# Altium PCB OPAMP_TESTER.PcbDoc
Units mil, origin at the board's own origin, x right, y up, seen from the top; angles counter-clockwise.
Board outline 7760.03 x 6155.03 mil, 2 copper layers (Top Layer, Bottom Layer); 148 components, 57 nets, 514 pads, 0 vias.
Unrouted connection lines stored in the file: 27.
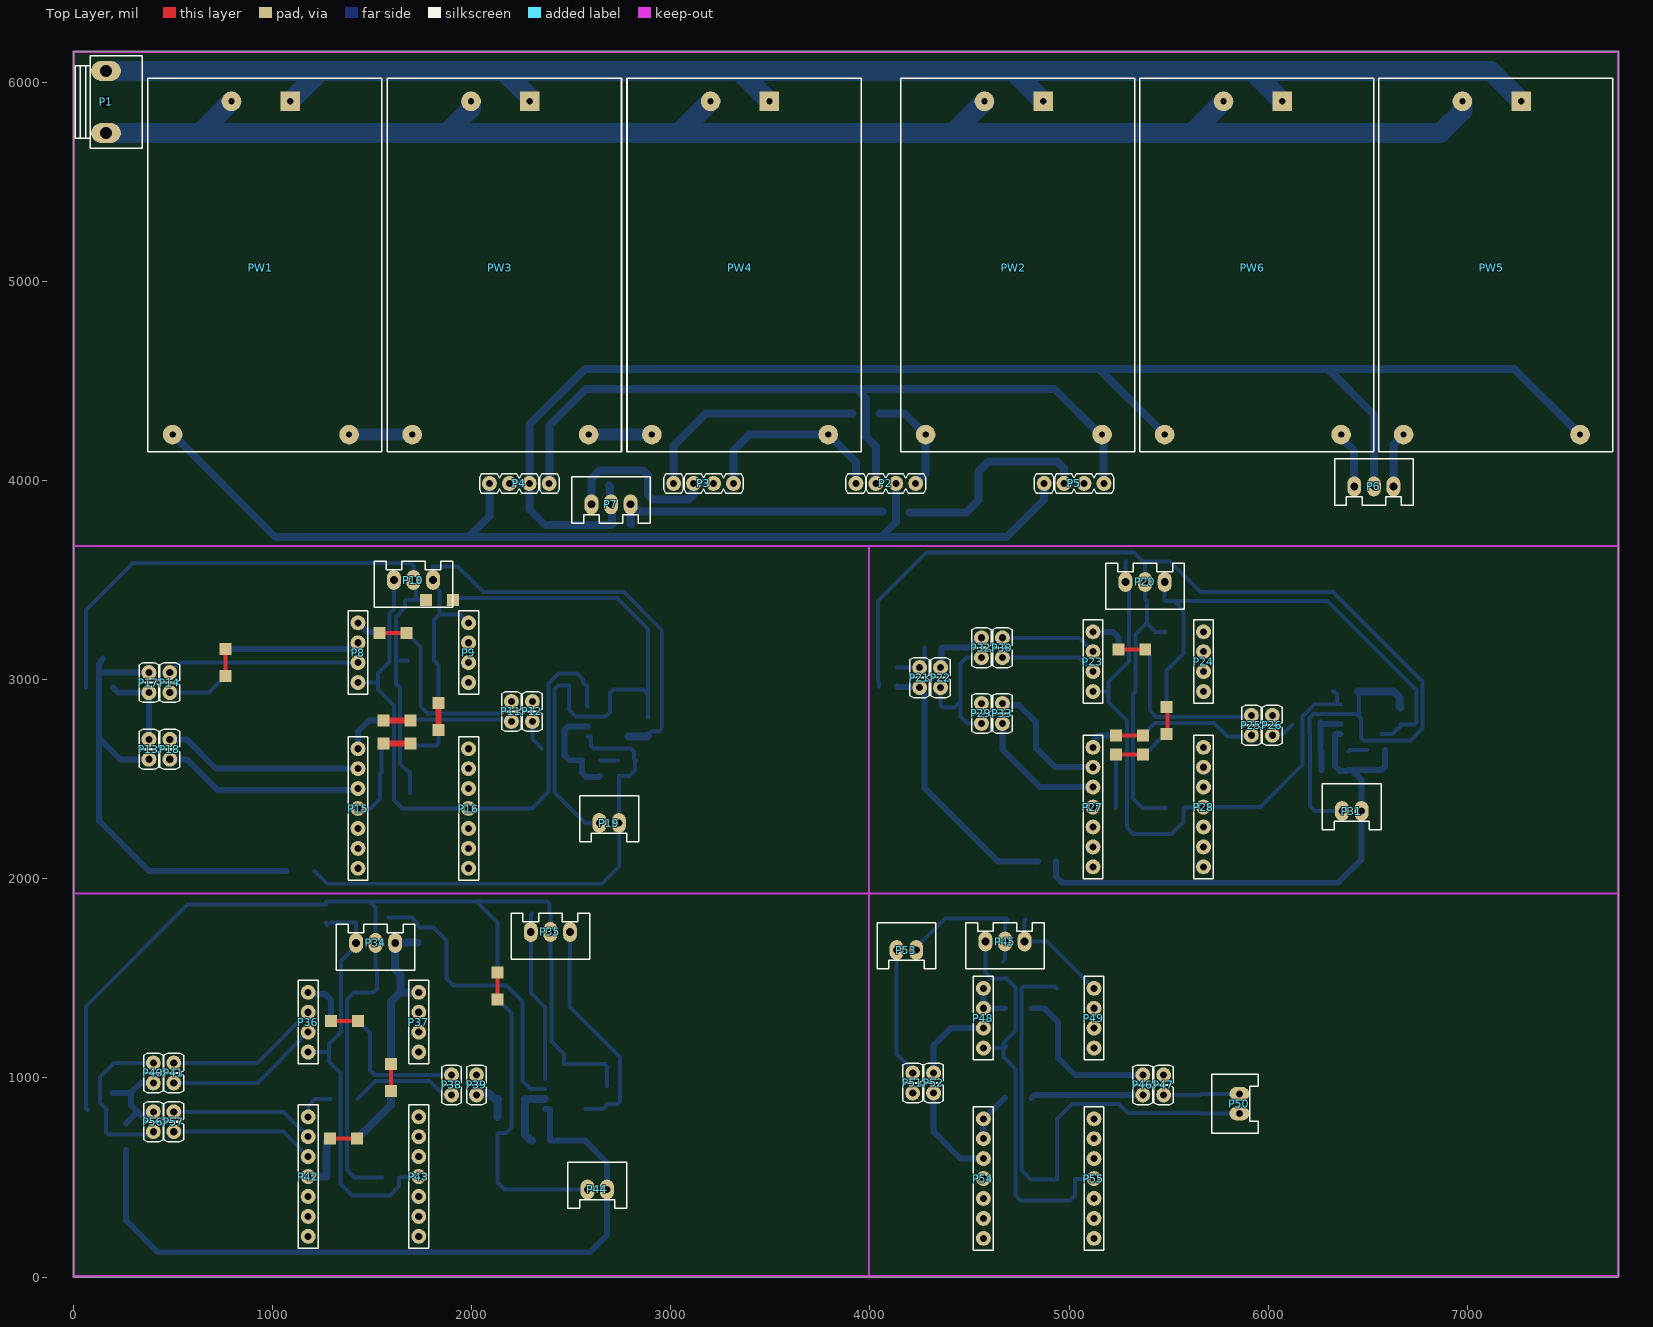
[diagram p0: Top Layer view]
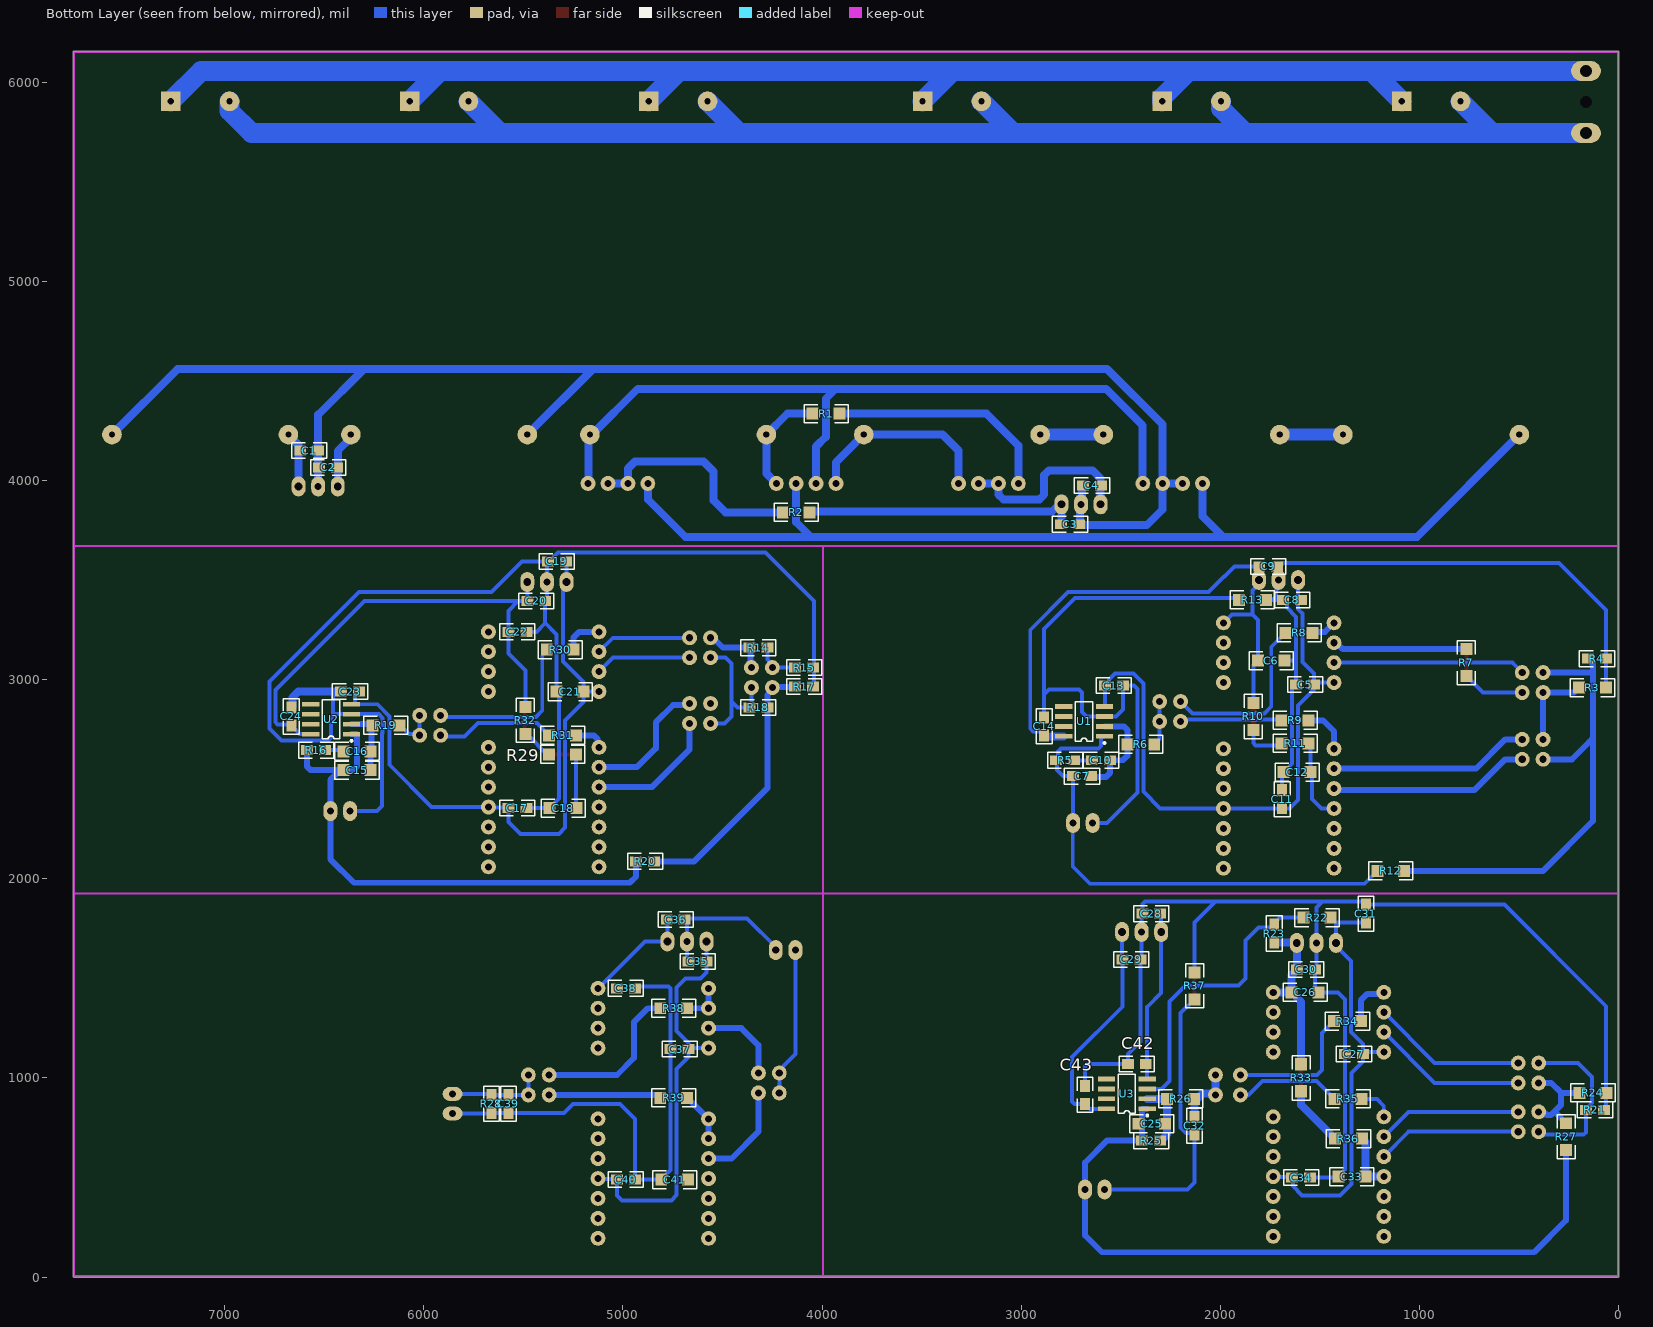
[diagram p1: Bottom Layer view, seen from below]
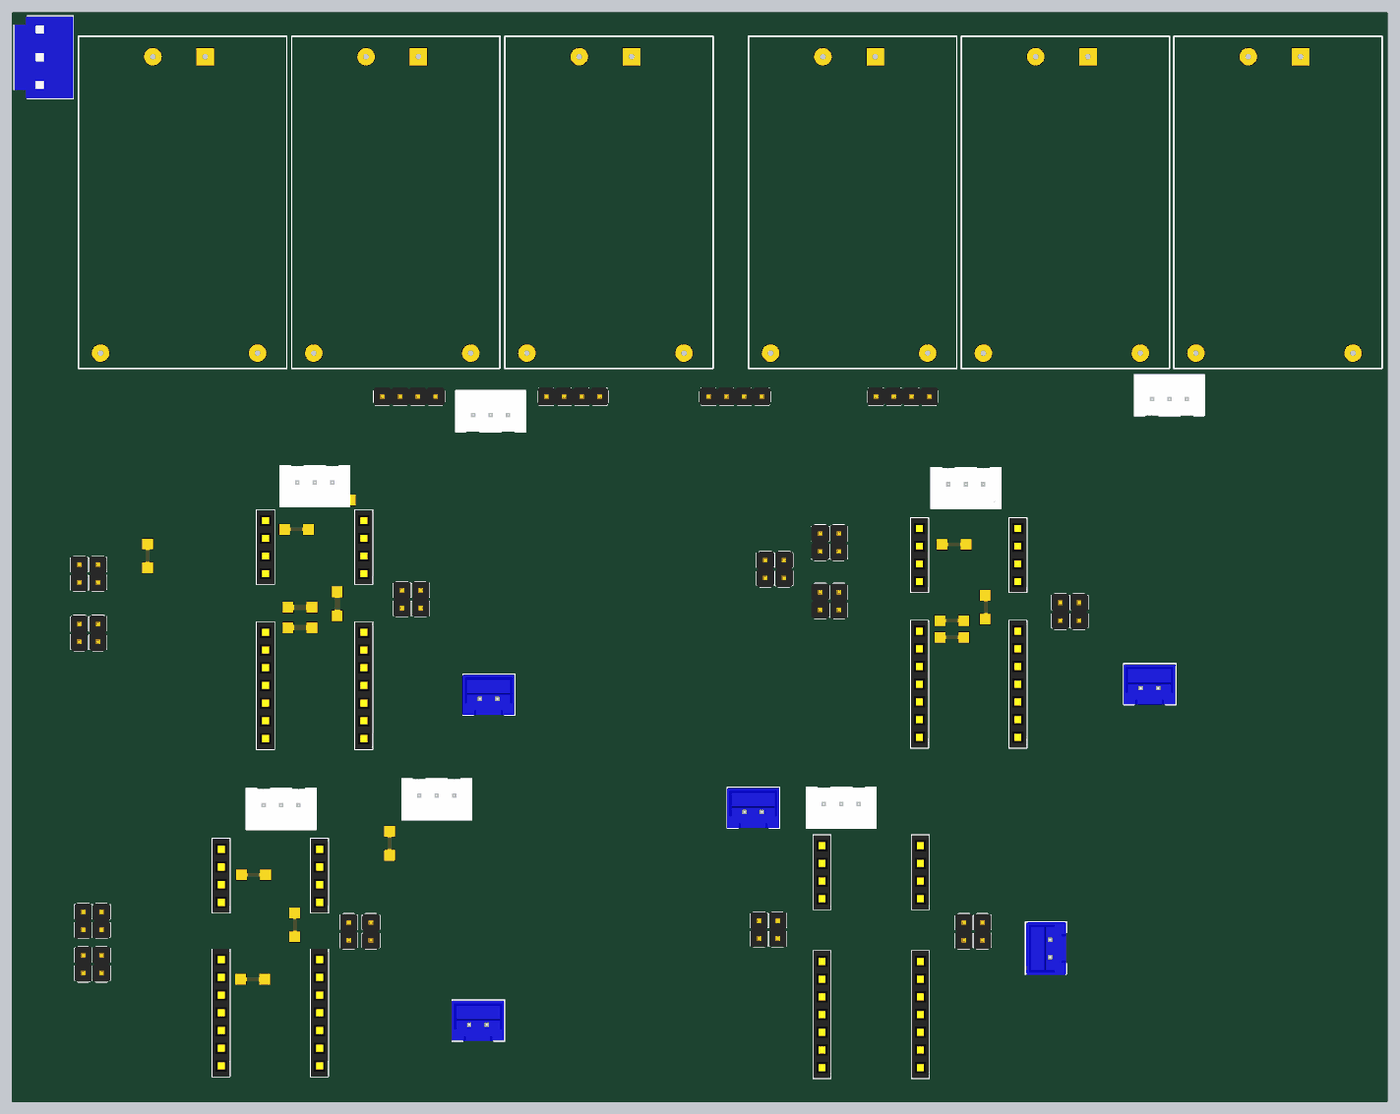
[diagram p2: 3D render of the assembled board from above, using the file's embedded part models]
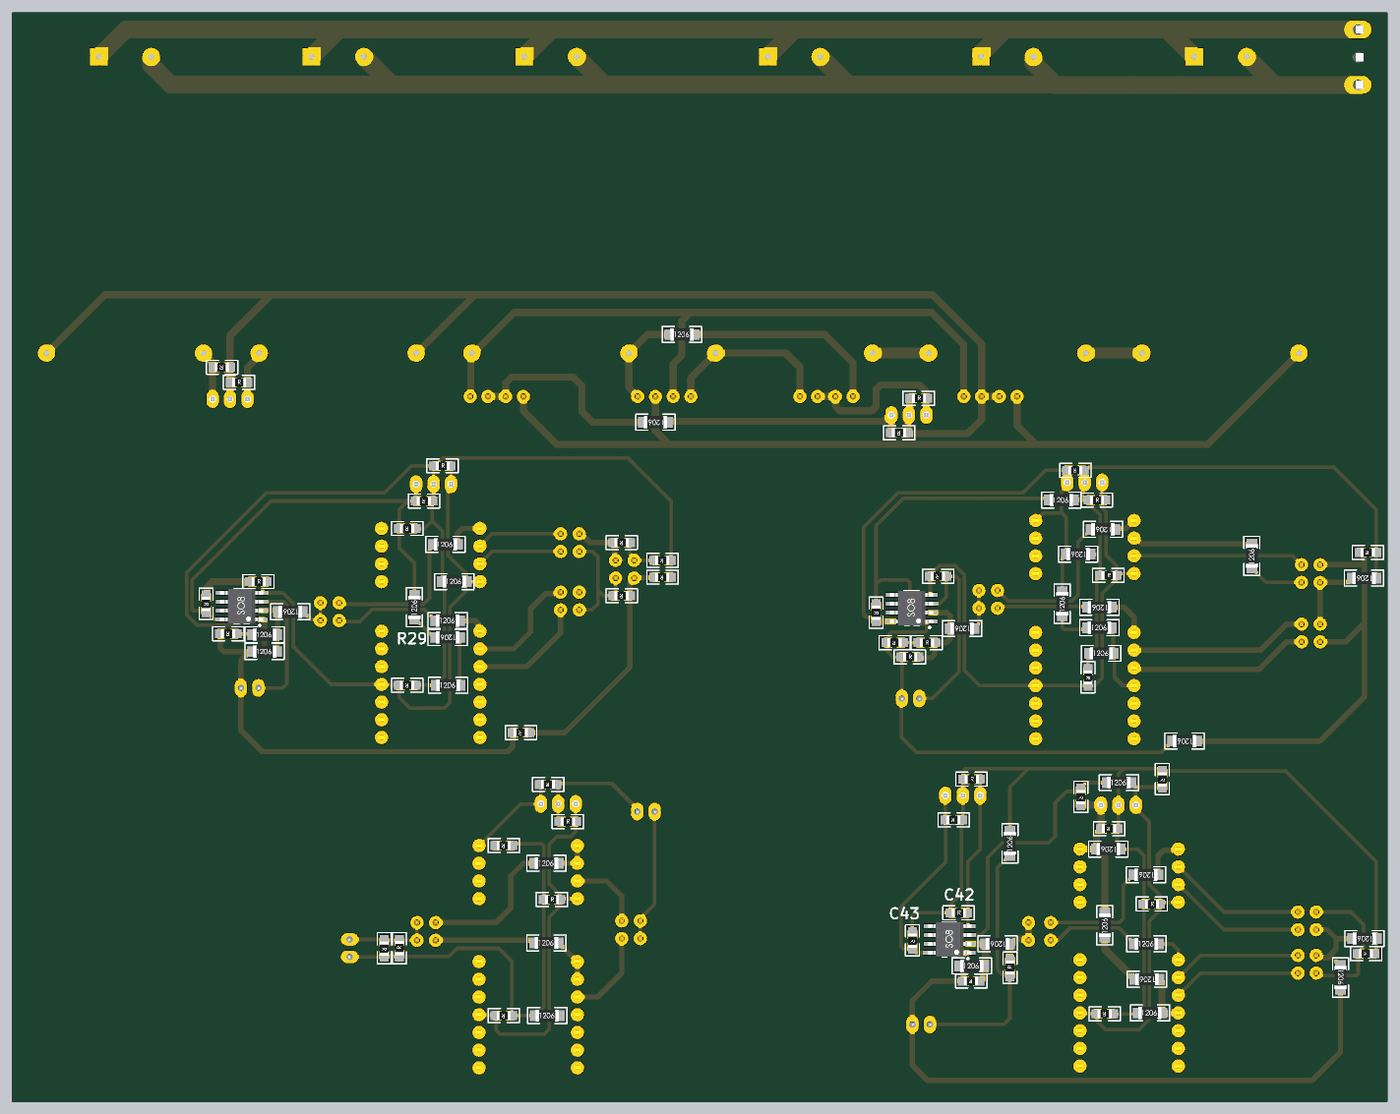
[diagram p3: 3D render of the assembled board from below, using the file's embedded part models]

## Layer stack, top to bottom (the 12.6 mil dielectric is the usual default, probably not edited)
Top Solder: solder mask 0.4, Solder Resist, Dk 3.5
Top Layer: signal copper 1.4
Dielectric 1: dielectric 12.6, FR-4, Dk 4.8
Bottom Layer: signal copper 1.4
Bottom Solder: solder mask 0.4, Solder Resist, Dk 3.5

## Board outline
5,-0.01 cw(c5,5) -0.01,5 -0.01,6150 cw(c5,6150) 5,6155.02 7755,6155.02 cw(c7755,6150) 7760.02,6150 7760.02,5 cw(c7755,5) 7755,-0.01

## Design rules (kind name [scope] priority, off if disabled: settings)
Clearance [All] p1: gap=10 ignorepadtopadclearanceinfootprint=FALSE except(0: Arc-Hole Track-Hole SMDPad-Hole THPad-Hole Via-Hole Fill-Hole Poly-Hole Region-Hole Text-Hole)
PolygonConnect [All] p1: connectstyle=Relief reliefconductorwidth=10 reliefentries=4 polygonreliefangle="90 Angle" airgapwidth=10
RoutingVias [All] p1: holewidth=28 width=50 viastyle="Through Hole" minholewidth=28 minwidth=50 maxholewidth=50 maxwidth=500
SolderMaskExpansion [All] p1: expansion=4 istentingtop=FALSE
Width [All] p1: maxlimit=100 minlimit=10 preferedwidth=10
30 further rules are at their usual default settings.

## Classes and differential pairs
component class OPAMP_TESTER: C1 C2 C3 C4 P1 P2 P3 P4 P5 P6 P7 PW1 PW2 PW3 PW4 PW5 PW6 R1 R2
component class OPAMP_TESTER_2: C25 C26 C27 C28 C29 C30 C31 C32 C33 C34 C35 C36 C37 C38 C39 C40 C41 C42 C43 P34 P35 P36 P37 P38 P39 P40 P41 P42 P43 P44 P45 P46 P47 P48 P49 P50 P51 P52 P53 P54 P55 P56 P57 R21 R22 R23 R24 R25 R26 R27 R28 R33 R34 R35 R36 R37 R38 R39 U3
component class OPAMP_TESTER_1: C5 C6 C7 C8 C9 C10 C11 C12 C13 C14 C15 C16 C17 C18 C19 C20 C21 C22 C23 C24 P8 P9 P10 P11 P12 P13 P14 P15 P16 P17 P18 P19 P20 P21 P22 P23 P24 P25 P26 P27 P28 P29 P30 P31 P32 P33 R3 R4 R5 R6 R7 R8 R9 R10 R11 R12 R13 R14 R15 R16 R17 R18 R19 R20 R29 R30 R31 R32 U1 U2

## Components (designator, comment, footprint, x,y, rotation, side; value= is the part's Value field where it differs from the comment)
C1 "100nF" "SMD 0805" 6575,4150 r0 bottom
C2 "100nF" "SMD 0805" 6480,4065 r180 bottom
C3 "100nF" "SMD 0805" 2755,3780 r0 bottom
C4 "100nF" "SMD 0805" 2645,3975 r180 bottom
C5 "100nF" "SMD 0805" 1575,2975 r180 bottom
C6 "100nF" "SMD 1206" 1745,3095 r0 bottom
C7 "1uF" "SMD 0805" 2695,2515 r180 bottom
C8 "100nF" "SMD 0805" 1640,3400 r180 bottom
C9 "100nF" "SMD 0805" 1760.21,3568.31 r0 bottom
C10 "1uF" "SMD 0805" 2600,2595 r180 bottom
C11 "100nF" "SMD 0805" 1690,2400 r270 bottom
C12 "100nF" "SMD 1206" 1615,2535 r180 bottom
C13 "100nF" "SMD 0805" 2535,2970 r0 bottom
C14 "100nF" "SMD 0805" 2885,2765 r270 bottom
C15 "1uF" "SMD 1206" 6335,2545 r180 bottom
C16 "1uF" "SMD 1206" 6335,2640 r180 bottom
C17 "100nF" "SMD 0805" 5530,2355 r0 bottom
C18 "100nF" "SMD 1206" 5300,2355 r180 bottom
C19 "100nF" "SMD 0805" 5331.66,3593.67 r180 bottom
C20 "100nF" "SMD 0805" 5435,3395 r0 bottom
C21 "100nF" "SMD 1206" 5265,2940 r180 bottom
C22 "100nF" "SMD 0805" 5530,3240 r0 bottom
C23 "100nF" "SMD 0805" 6370,2940 r180 bottom
C24 "100nF" "SMD 0805" 6665,2815 r270 bottom
C25 "1uF" "SMD 1206" 2345,770 r180 bottom
C26 "100nF" "SMD 1206" 1575,1430 r0 bottom
C27 "100nF" "SMD 0805" 1330,1120 r180 bottom
C28 "100nF" "SMD 0805" 2347.5,1824.77 r180 bottom
C29 "100nF" "SMD 0805" 2447.5,1594.77 r0 bottom
C30 "100nF" "SMD 0805" 1570,1545 r0 bottom
C31 "100nF" "SMD 0805" 1270,1825 r270 bottom
C32 "1uF" "SMD 0805" 2130,760 r90 bottom
C33 "100nF" "SMD 1206" 1340,505 r180 bottom
C34 "100nF" "SMD 0805" 1595,500 r0 bottom
C35 "100nF" "SMD 0805" 4625,1585 r180 bottom
C36 "100nF" "SMD 0805" 4735,1795 r0 bottom
C37 "100nF" "SMD 0805" 4715,1145 r180 bottom
C38 "100nF" "SMD 0805" 4985,1450 r0 bottom
C39 "100pF" "SMD 0805" 5575,870 r90 bottom
C40 "100nF" "SMD 0805" 4985,490 r0 bottom
C41 "100nF" "SMD 1206" 4740,490 r180 bottom
C42 "100nF" "SMD 0805" 2420,1070 r180 bottom
C43 "100nF" "SMD 0805" 2680,915 r270 bottom
P1 "CONNECTOR 3" "CON VH 3" 165,5744.09 r90 top
P2 "CONNECTOR 4" "CON HDR 2.54M 4" 3930,3985 r0 top
P3 "CONNECTOR 4" "CON HDR 2.54M 4" 3015,3985 r0 top
P4 "CONNECTOR 4" "CON HDR 2.54M 4" 2390,3985 r180 top
P5 "CONNECTOR 4" "CON HDR 2.54M 4" 4875,3985 r0 top
P6 "INPUT_12+-V" "CON XH 3" 6628.43,3970 r180 top
P7 "INPUT_12+-V" "CON XH 3" 2798.43,3880 r180 top
P8 "LM358_DUT" "CON HDR 2.54FM 4" 1430,3285 r270 top
P9 "LM358DUT" "CON HDR 2.54FM 4" 1985,3285 r270 top
P10 "INPUT_12+-V" "CON XH 3" 1610,3500 r0 top
P11 "CONNECTOR 2" "CON HDR 2.54M 2" 2200,2890 r270 top
P12 "CONNECTOR 2" "CON HDR 2.54M 2" 2305,2790 r90 top
P13 "CONNECTOR 2" "CON HDR 2.54M 2" 380,2700 r270 top
P14 "CONNECTOR 2" "CON HDR 2.54M 2" 485,3035 r270 top
P15 "LM324_DUT" "CON HDR 2.54FM 7" 1430,2652.78 r270 top
P16 "LM324_DUT" "CON HDR 2.54FM 7" 1985,2652.78 r270 top
P17 "CONNECTOR 2" "CON HDR 2.54M 2" 380,2935 r90 top
P18 "CONNECTOR 2" "CON HDR 2.54M 2" 485,2600 r90 top
P19 "SAMPLE_OUT" "CON XH 2" 2740,2280 r180 top
P20 "INPUT_12+-V" "CON XH 3" 5283.15,3490 r0 top
P21 "CONNECTOR 2" "CON HDR 2.54M 2" 4250,3060 r270 top
P22 "CONNECTOR 2" "CON HDR 2.54M 2" 4355,2960 r90 top
P23 "LM358_DUT" "CON HDR 2.54FM 4" 5120,3240 r270 top
P24 "LM358DUT" "CON HDR 2.54FM 4" 5675,3240 r270 top
P25 "CONNECTOR 2" "CON HDR 2.54M 2" 5915,2820.49 r270 top
P26 "CONNECTOR 2" "CON HDR 2.54M 2" 6020.16,2720.49 r90 top
P27 "LM324_DUT" "CON HDR 2.54FM 7" 5120,2660 r270 top
P28 "LM324_DUT" "CON HDR 2.54FM 7" 5675,2660 r270 top
P29 "CONNECTOR 2" "CON HDR 2.54M 2" 4560,2880 r270 top
P30 "CONNECTOR 2" "CON HDR 2.54M 2" 4665,3110 r90 top
P31 "SAMPLE_OUT" "CON XH 2" 6468.43,2340 r180 top
P32 "CONNECTOR 2" "CON HDR 2.54M 2" 4560,3210 r270 top
P33 "CONNECTOR 2" "CON HDR 2.54M 2" 4665,2780 r90 top
P34 "INPUT_25V,5V" "CON XH 3" 1420,1678.19 r0 top
P35 "INPUT_12+-V" "CON XH 3" 2297.46,1732.96 r0 top
P36 "LM358_DUT" "CON HDR 2.54FM 4" 1180,1430 r270 top
P37 "LM358DUT" "CON HDR 2.54FM 4" 1735,1430 r270 top
P38 "CONNECTOR 2" "CON HDR 2.54M 2" 1900,1015 r270 top
P39 "CONNECTOR 2" "CON HDR 2.54M 2" 2025,1015 r270 top
P40 "CONNECTOR 2" "CON HDR 2.54M 2" 402.33,1075 r270 top
P41 "CONNECTOR 2" "CON HDR 2.54M 2" 505,975 r90 top
P42 "LM324_DUT" "CON HDR 2.54FM 7" 1180,805 r270 top
P43 "LM324_DUT" "CON HDR 2.54FM 7" 1735,805 r270 top
P44 "SAMPLE_OUT" "CON XH 2" 2680,440 r180 top
P45 "INPUT_12+-V" "CON XH 3" 4580,1685 r0 top
P46 "CONNECTOR 2" "CON HDR 2.54M 2" 5370,1015 r270 top
P47 "CONNECTOR 2" "CON HDR 2.54M 2" 5475,915 r90 top
P48 "LM358_DUT" "CON HDR 2.54FM 4" 4570,1450 r270 top
P49 "LM358DUT" "CON HDR 2.54FM 4" 5125,1450 r270 top
P50 "SAMPLE_OUT" "CON XH 2" 5855,920 r270 top
P51 "CONNECTOR 2" "CON HDR 2.54M 2" 4215,925 r90 top
P52 "CONNECTOR 2" "CON HDR 2.54M 2" 4320,925 r90 top
P53 "INPUT_15V_100KHz" "CON XH 2" 4232.73,1641.69 r180 top
P54 "LM324_DUT" "CON HDR 2.54FM 7" 4570,795 r270 top
P55 "LM324_DUT" "CON HDR 2.54FM 7" 5125,795 r270 top
P56 "CONNECTOR 2" "CON HDR 2.54M 2" 402.33,730 r90 top
P57 "CONNECTOR 2" "CON HDR 2.54M 2" 505,730 r90 top
PW1 "15V_PW" POW 1090,6018.23 r270 top
PW2 "5V_PW" POW 4870.28,6018.23 r270 top
PW3 "15V_PW" POW 2292.78,6018.23 r270 top
PW4 "15V_PW" POW 3495.55,6018.23 r270 top
PW5 "15V_PW" POW 7270,6018.23 r270 top
PW6 "15V_PW" POW 6070.47,6018.23 r270 top
R1 "0R" "SMD 1206" 3980,4335 r180 bottom
R2 "0R" "SMD 1206" 4130,3840 r0 bottom
R3 "200R_1%" "SMD 1206" 132.5,2959.85 r0 bottom
R4 "200R_1%" "SMD 0805" 110,3105 r0 bottom
R5 "4.3K" "SMD 0805" 2780,2595 r0 bottom
R6 "4.3K" "SMD 1206" 2400,2675 r0 bottom
R7 "0R" "SMD 1206" 765,3085 r90 bottom
R8 "0R" "SMD 1206" 1605,3235 r0 bottom
R9 "0R" "SMD 1206" 1625,2795 r0 bottom
R10 "0R" "SMD 1206" 1835,2815 r90 bottom
R11 "0R" "SMD 1206" 1625,2680 r180 bottom
R12 "24K_1%" "SMD 1206" 1145,2040 r0 bottom
R13 "0R" "SMD 1206" 1840,3400 r180 bottom
R14 "1Meg" "SMD 0805" 4320,3160 r0 bottom
R15 "100R" "SMD 0805" 4090,3060 r0 bottom
R16 "10K" "SMD 0805" 6540,2645.63 r0 bottom
R17 "100R" "SMD 0805" 4090,2965 r0 bottom
R18 "1Meg" "SMD 0805" 4320,2860 r0 bottom
R19 "10K" "SMD 1206" 6190,2770 r0 bottom
R20 "10K" "SMD 0805" 4888.51,2087.64 r0 bottom
R21 "100R" "SMD 0805" 120,840 r0 bottom
R22 "20K" "SMD 1206" 1515,1805 r180 bottom
R23 "20K" "SMD 0805" 1730,1725 r270 bottom
R24 "100R" "SMD 1206" 130,925 r0 bottom
R25 "10K" "SMD 0805" 2348.19,685 r0 bottom
R26 "10K" "SMD 1206" 2200,895 r0 bottom
R27 "10K" "SMD 1206" 265,705 r270 bottom
R28 "2K" "SMD 0805" 5660,870 r270 bottom
R29 "0R" "SMD 1206" 5302.5,2625 r0 bottom
R30 "0R" "SMD 1206" 5315,3150 r180 bottom
R31 "0R" "SMD 1206" 5302.5,2720 r180 bottom
R32 "0R" "SMD 1206" 5490,2795 r90 bottom
R33 "0R" "SMD 1206" 1595,1000 r90 bottom
R34 "0R" "SMD 1206" 1362.5,1285 r0 bottom
R35 "0R" "SMD 1206" 1360,895 r180 bottom
R36 "0R" "SMD 1206" 1357.5,695 r0 bottom
R37 "0R" "SMD 1206" 2130,1462.5 r90 bottom
R38 "0R" "SMD 1206" 4745,1350 r180 bottom
R39 "0R" "SMD 1206" 4745,900 r180 bottom
U1 "IC LM358" "SMD IC SOP8" 2685,2790 r90 bottom
U2 "IC LM358" "SMD IC SOP8" 6465,2801.18 r90 bottom
U3 "IC LM358" "SMD IC SOP8" 2470,920 r90 bottom

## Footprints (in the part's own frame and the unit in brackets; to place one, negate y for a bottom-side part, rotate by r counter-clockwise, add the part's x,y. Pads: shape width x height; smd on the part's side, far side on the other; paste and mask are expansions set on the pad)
"CON HDR 2.54FM 4" [mm] "CONNECTOR PTCH:2.54MM"
  round 1.905 hole 0.9: 1(0,0) 2(2.54,0) 3(5.08,0) 4(7.62,0)
  silkscreen extent -1.52,-1.27 9.14,1.27, body extent -1.5,-1.24 9.16,1.26, height 5
"CON HDR 2.54FM 7" [mm] "CONNECTOR PTCH:2.54MM"
  round 1.905 hole 0.9: 1(0,0) 2(2.54,0) 3(5.08,0) 4(7.62,0) 5(10.16,0) 6(12.7,0) 7(15.24,0)
  silkscreen extent -1.52,-1.27 16.76,1.27, body extent -1.54,-1.24 16.74,1.26, height 5
"CON HDR 2.54M 2" [mm] "CONNECTOR PTCH:2.54MM"
  round 1.905 hole 0.9: 1(0,0) 2(2.54,0)
  silkscreen extent -1.27,-1.25 3.81,1.25, body extent -1.27,-1.27 3.81,1.27, height 8.89
"CON HDR 2.54M 4" [mm] "CONNECTOR PTCH:2.54MM"
  round 1.905 hole 0.9: 1(0,0) 2(2.54,0) 3(5.08,0) 4(7.62,0)
  silkscreen extent -1.27,-1.25 8.89,1.25, body extent -1.27,-1.27 8.89,1.27, height 8.89
"CON VH 3" [mm] "CONNECTOR PITCH:3.96MM"
  oval 2.54x3.81 hole 1.5: 1(0,0) 3(7.92,0)
  round 0 hole 1.5: 2(3.96,0)
  silkscreen extent -1.95,-4.6 9.87,3.9, body extent -1.95,-4.6 9.87,3.9, height 10.9
"CON XH 2" [mm] "CONNECTOR PITCH:2.5MM"
  oval 1.778x2.54 hole 0.9: 1(0,0) 2(2.5,0)
  silkscreen extent -2.5,-3.5 5,2.4, body extent -2.45,-3.35 5.05,2.35, height 7
"CON XH 3" [mm] "CONNECTOR PITCH:2.5MM"
  oval 1.778x2.54 hole 1: 1(0,0) 3(5,0)
  oval 1.778x2.54 hole 0.9: 2(2.5,0)
  silkscreen extent -2.5,-3.5 7.5,2.4, body extent -2.46,-3.41 7.44,2.34, height 7
POW [mm]
  rect 2.5x2.5 hole 0.8: 1(2.921,0)
  round 2.5 hole 0.8: 2(2.921,-7.5) 3(45.421,-15) 4(45.421,7.5)
  silkscreen extent 0,-18.16 47.63,11.68
"SMD 0805" [mil] "SMD 0805"
  round 27.56 on Mech2: 0(0,0)
  rect 60x50 smd: 1(-45,0) 2(45,0)
  silkscreen extent -88,-39 88,39, body extent -57,-28 61,27, height 21
"SMD 1206" [mil] "SMD 1206"
  round 27.56 on Mech2: 0(0,0)
  rect 60x60 smd: 1(-67.5,0) 2(67.5,0)
  silkscreen extent -111,-45 111,45, body extent -66,-34 66,34, height 33
"SMD IC SOP8" [mm] "SOP, 8-Leads , Pitch 1.27mm"
  rect 0.6x2.2 smd: 1(-1.905,-2.6) 2(-0.635,-2.6) 3(0.635,-2.6) 4(1.905,-2.6) 5(1.905,2.6) 6(0.635,2.6) 7(-0.635,2.6) 8(-1.905,2.6)
  round 1.5 on Mech2: 4(-1.3,0) 4(1.3,0)
  silkscreen extent -2.88,-2.72 2.5,1.1, body extent -2.5,-3.1 2.5,3.1, height 1.75

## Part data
C1 C2 C3 C4 C5 C6 C7 C8 C9 C10 C11 C12 C13 C14 C15 C16 C17 C18 C19 C20 C21 C22 C23 C24 C25 C26 C27 C28 C29 C30 C31 C32 C33 C34 C35 C36 C37 C38 C39 C40 C41 C42 C43: library part CAP, "Capacitor"
P1: "Header, 3-Pin"
P2 P3 P4 P5: "Header, 4-Pin"
P6 P7 P10 P20 P34 P35 P45: library part "CONNECTOR 3", "Header, 3-Pin"
P8 P9 P23 P24 P36 P37 P48 P49: library part "CONNECTOR 4", "Header, 4-Pin"
P11 P12 P13 P14 P17 P18 P21 P22 P25 P26 P29 P30 P32 P33 P38 P39 P40 P41 P46 P47 P51 P52 P56 P57: "Header, 2-Pin"
P15 P16 P27 P28 P42 P43 P54 P55: library part "CONNECTOR 7", "Header, 7-Pin"
P19 P31 P44 P50 P53: library part "CONNECTOR 2", "Header, 2-Pin"
PW1 PW2 PW3 PW4 PW5 PW6: library part POWER
R1 R2 R3 R4 R5 R6 R7 R8 R9 R10 R11 R12 R13 R14 R15 R16 R17 R18 R19 R20 R21 R22 R23 R24 R25 R26 R27 R28 R29 R30 R31 R32 R33 R34 R35 R36 R37 R38 R39: library part RES, "Resistor"

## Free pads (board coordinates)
  rect 60x60 all layers, no hole: 2(765,3017.5) 2(765,3152.5) 2(1290,695) 2(1295,1285) 2(1425,695) 2(1430,1285) 2(1537.5,3235) 2(1557.5,2680) 2(1557.5,2795) 2(1595,935) 2(1595,1070) 2(1672.5,3235) 2(1692.5,2680) 2(1692.5,2795) 2(1772.5,3400) 2(1835,2747.5) 2(1835,2882.5) 2(1907.5,3400) 2(2130,1395) 2(2130,1530) 2(5235,2625) 2(5235,2720) 2(5247.5,3150) 2(5370,2625) 2(5370,2720) 2(5382.5,3150) 2(5490,2727.5) 2(5490,2862.5)

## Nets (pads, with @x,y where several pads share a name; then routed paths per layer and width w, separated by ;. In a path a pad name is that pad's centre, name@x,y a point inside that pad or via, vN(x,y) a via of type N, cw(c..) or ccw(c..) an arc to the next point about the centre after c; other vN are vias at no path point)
5+: P2.4 P3.1 PW2.3 R1.1 R1.2 | length 1710.1
  Bottom Layer w40: P3.1@3015,3970 3015,4175 3175,4335 R1.2 ; R1.1 4174.72,4335 PW2.3 4279.72,4034.72 P2.4
5-: P2.2 P4.1 P5.4 PW2.4 | length 4020.6
  Bottom Layer w40: P4.1@2390.67,3975 2390.67,4275.67 2575,4460 3931.26,4460 ; P2.2@4030,3975.31 P2.2 4030,4170 3981.26,4218.74 3981.26,4410 3931.26,4460 ; P5.4@5172.52,3985 5172.52,4223.03 PW2.4 5155.15,4230 4925.15,4460 3931.26,4460
25+: P2.1 P3.4 PW4.4 | length 1000.2
  Bottom Layer w40: P3.4@3315,3970 3315,4150 3395,4230 PW4.4 3930,4090.83 P2.1@3930,3976.44
25-: P2.3 P4.4 P5.1 PW1.3 | length 5362.1
  Bottom Layer w40: PW1.3 1014.45,3715 1985,3715 ; P4.4 2090,3820 1985,3715 ; P2.3 4130,3790 4055,3715 ; P5.1 4875,3905 4685,3715 4055,3715 ; 1985,3715 4055,3715
+15: C2.2 C6.2 C9.2 C12.2 C14.2 C18.2 C20.2 C22.2 C24.2 C29.2 C36.2 C38.2 C41.2 C43.2 P6.3 P9.1 P10.3 P15.4 P20.3 P24.1 P27.4 P35.3 P45.3 P49.1 P54.4 pad.2@1557.5,2680 pad.2@1692.5,2680 pad.2@1835,2747.5 pad.2@1835,2882.5 pad.2@5235,2625 pad.2@5370,2625 pad.2@5490,2727.5 pad.2@5490,2862.5 PW6.4 R10.1 R10.2 R11.1 R11.2 R29.1 R29.2 R32.1 R32.2 U1.8 U2.8 U3.8 | length 8946.1
  Top Layer w20: pad.2@5232.5,2625 pad.2@5367.5,2625 ; pad.2@5495,2742.5 pad.2@5495,2877.5
  Top Layer w30: pad.2@1557.5,2680 pad.2@1692.5,2680 ; pad.2@1835,2747.5 pad.2@1835,2882.5
  Bottom Layer w20: P15.4 1492.78,2352.78 1540,2400 1540,2527.5 C12.2 1547.5,2670 R11.2 ; R11.1 1702.5,2670 1823.28,2670 1835,2681.72 R10.1 ; C9.2 C9.2@1806.85,3568.31 ; R10.2 1835,3072.5 C6.2 1812.5,3300 1840,3327.5 ; P9.1 1942.5,3327.5 1840,3327.5 ; P35.3 2494.31,1596.58 C29.2 2492.5,1357.5 2745,1105 2745,881.72 2733.28,870 C43.2 2680,865 2665,850 2660,850 2655,845 U3.8 ; C14.2 2885,2725 2900,2740 2940,2740 2955,2755 2955,3250 2765,3440 2060,3440 1982.5,3517.5 1980.81,3517.5 1930,3568.31 C9.2@1806.85,3568.31 ; C36.2 4776.85,1791.85 P45.3 4890,1685 P49.1 ; C18.2 5235,2357.5 R29.1 ; pad.2@5370,2615 pad.2@5486.25,2731.25 ; P20.3 C20.2 6297.57,3395 6745,2947.57 6745,2785.86 6733.28,2774.14 6665,2774.14 6665,2765 6650,2750 6645,2750 6622.99,2727.99 6569.17,2727.99 U2.8 ; R32.2 5490,3045 5575,3130 C22.2 5575,3345 5528.28,3391.72 ; C9.2@1806.85,3568.31 P10.3 1806.85,3481.43 1840,3448.28 1840,3327.5
  Bottom Layer w40: U1.8 2880,2715 C14.2 ; PW6.4 6365.75,4214.19 6431.58,4148.36 P6.3
-15: C1.2 C5.2 C8.2 C11.2 C13.2 C17.2 C19.2 C21.2 C23.2 C28.2 C35.2 C37.2 C40.2 C42.2 P6.1 P8.4 P10.1 P16.4 P20.1 P23.4 P28.4 P35.1 P45.1 P48.4 P55.4 PW5.3 U1.4@2582.64,2865 U2.4@6362.64,2876.18 U3.4@2367.64,995 | length 9292
  Bottom Layer w20: P8.4 C5.2@1515,2985 ; C5.2@1520,2985 C5.2@1530,2985 ; P10.1 1610,3353.21 1587.5,3330.71 1587.5,3087.5 1530,3030 C5.2@1530,2985 ; C28.2 2297.46,1819.73 P35.1 2297.46,1427.54 2367.64,1357.36 U3.4@2367.64,995 ; U1.4@2582.64,2865 2581.81,2865 2580,2866.81 C13.2 2575,2970 2560,2985 2560,3000 2530,3030 2437.5,3030 2387.5,2980 2387.5,2437.5 2302.78,2352.78 P16.4 1650,2352.78 1650,2355 1610,2395 1610,2870 1530,2950 C5.2 C5.2@1530,2985 ; P48.4 C37.2@4665,1150 ; P45.1 C35.2 4580,1530 4610,1500 4685,1500 4730,1455 4730,1235 4670,1175 4670,1105 4730,1045 4730,411.72 4756.72,385 5005,385 5030,410 C40.2 5032.5,492.5 5122.5,492.5 P55.4 ; C37.2@4670,1155 4678.28,1155 C37.2@4683.28,1160 ; P23.4 C21.2 ; C19.2 5283.15,3590.17 5283.15,3461.47 5300,3444.62 5300,3090 5198.28,2988.28 5198.28,2940.78 C21.2 ; C23.2 6330,2940 6345,2925 6345,2877.99 U2.4@6346.81,2876.18 ; U2.4@6362.64,2876.18 U2.4@6346.81,2876.18 ; C21.2 5197.5,2887.5 5290,2795 5290,2256.72 5321.72,2225 5515,2225 5575,2285 C17.2 5577.5,2357.5 5672.5,2357.5 P28.4 5960,2360 6172.5,2572.5 6172.5,2815.71 6232.97,2876.18 U2.4@6346.81,2876.18
  Bottom Layer w40: P6.1 6628.43,4177.36 6679.45,4228.38 PW5.3
AC_INPUT: P51.1 P51.2 P53.2 | length 750.1
  Bottom Layer w20: P53.2 4134.31,1120.69 4194.77,1060.23 4194.77,1060.11 4215,1039.88 P51.1
CMRR_COMMON: P40.2 P56.2 R24.2 R27.1 | length 510.7
  Bottom Layer w30: R24.2 290,925 ; R27.1 315,822.5 315,840 ; P40.2@400,975 340,975 290,925 ; P56.2 393.72,821.39 368.65,821.39 362.26,815 340,815 315,840 ; 290,925 290,865 315,840
GND: C1.1 C2.1 C3.1 C4.1 C5.1 C6.1 C8.1 C9.1 C11.1 C12.1 C13.1 C14.1 C17.1 C18.1 C19.1 C20.1 C21.1 C22.1 C23.1 C24.1 C26.1 C27.1 C28.1 C29.1 C30.1 C31.1 C32.1 C33.1 C34.1 C35.1 C36.1 C37.1 C38.1 C39.1 C40.1 C41.1 C42.1 C43.1 P4.2 P4.3 P6.2 P7.2 P10.2 P19.2 P20.2 P31.2 P34.2 P35.2 P44.2 P45.2 P50.2 P53.1 pad.2@1772.5,3400 pad.2@1907.5,3400 pad.2@2130,1395 pad.2@2130,1530 PW5.4 PW6.3 R3.1 R4.1 R13.1 R13.2 R15.1 R17.1 R21.1 R24.1 R28.2 R37.1 R37.2 U1.3 U2.3 | length 32585.7
  Top Layer w20: pad.2@2130,1395 pad.2@2130,1530
  Bottom Layer w20: R3.1 R4.1 65,3350 300,3585 1683.5,3585 1685.19,3583.31 1695.21,3583.31 C9.1@1710.21,3568.31 ; R21.1 65,850 65,1360 575,1870 C31.1 ; C31.1@1270,1885 1488.43,1885 ; C30.1@1518.43,1551.57 P34.2 1518.43,1855 1488.43,1885 ; C30.1 1525,1447.5 C26.1 1410,1430 1375,1395 C27.1 1375,540 1387.5,527.5 1387.5,525 1412.5,500 C34.1 ; C5.1 1620,3090 ; C5.1@1622.5,2972.5 1627.5,2972.5 1640,2960 1640,2577.5 C12.1 ; C8.1@1670.93,3400 1666.29,3395.36 1666.29,3361.29 1620,3315 1620,3090 ; C6.1 1625,3095 1620,3090 ; C8.1 1740,3400 ; C11.1@1690,2430 C11.1 C12.1@1690,2535 ; C9.1@1708.43,3568.31 P10.2 1717.99,3490.43 1717.99,3450.29 1720,3448.28 1720,3420 1740,3400 ; R13.2 1740,3400 ; pad.2@1907.5,3410 2730,3410 2885,3255 2885,2925 ; R37.1 2200,1325 2200,750 2173.28,723.28 2138.28,723.28 C32.1 2130,475 2165,440 P44.2 ; R37.2 2130,1780 2025,1885 ; P19.2 2570,2280 2417.5,2432.5 2417.5,2952.5 2435,2970 C13.1 2490,2850 2525,2815 U1.3 2671.57,2815 2695,2838.43 2695,2935 2710,2950 2860,2950 2885,2925 ; C43.1 2680,1058.28 2668.28,1070 C42.1 2465,1120 2402.5,1182.5 C29.1 2395.88,1601.38 P35.2 2395.88,1821.38 C28.1 2392.5,1872.5 2380,1885 2025,1885 ; C14.1 2885,2925 ; R17.1 4045,2985 4040,2990 4040,3395 4283.67,3638.67 5326.66,3638.67 5371.66,3593.67 C19.1 ; P53.1 4232.73,1656.69 4376.04,1800 4685,1800 C36.1 4678.43,1783.43 P45.2 4678.43,1593.43 C35.1 ; C38.1 4930,1460 4771.72,1460 4760,1448.28 4760,537.5 C41.1 C40.1 4940,795 5015,870 5250,870 5295,825 C39.1 R28.2 5663.43,821.57 P50.2 ; C17.1 C18.1 5320,2402.5 5320,2927.5 C21.1 5332.5,3227.5 5390,3285 ; C22.1 5435,3240 5390,3285 ; P31.2 6235,2340 6210,2365 6210,2729.22 6207.5,2731.72 6207.5,2808.28 6225.4,2826.18 U2.3 6443.82,2826.18 6454.41,2815.59 ; 6450,2940 6454.41,2935.59 6454.41,2815.59 ; 1488.43,1885 2025,1885 ; C19.1 5381.58,3588.76 P20.2 5381.58,3403.43 C20.1 5390,3285 ; C19.1 5506.33,3593.67 5660,3440 6325,3440 6775,2990 6775,2755 6714.37,2694.37 6480.63,2694.37 6465,2710 6465,2805 6454.41,2815.59
  Bottom Layer w40: P4.3 P4.2 ; C4.1 2695,3970 2695,3885 P7.2 2705,3875 2705,3785 C3.1 ; C3.1@2700,3775 2370,3775 2290,3855 P4.2 ; PW6.3 5149.92,4560 ; 6450,2940 6630,2940 6660,2910 6660,2865 C24.1 ; P6.2 C1.1 6530,4330 6300,4560 ; PW5.4 7235.28,4560 6300,4560 ; P4.2 2290,4280 2570,4560 5149.92,4560 ; 5149.92,4560 6300,4560
GND_MAKER: R22.1 R23.1 U3.3 | length 1487.8
  Bottom Layer w20: R22.1 1700,1805 1730,1775 R23.1 ; R23.1@1730,1765 1740,1755 1810,1755 1875,1690 1875,1500 1910,1465 2175,1465 2255,1385 2255,985 2295,945 U3.3
IN+_CMRR_1: P36.3 P41.1 | length 780.6
  Bottom Layer w20: P41.1 925,975 P36.3
IN+_CMRR_2: P42.3 P57.1 | length 726.8
  Bottom Layer w20: P57.1 1055,730 P42.3
IN+_GBP_1: P48.3 P52.2 | length 425.2
  Bottom Layer w30: P52.2 4320,1165 4405,1250 P48.3
IN+_GBP_2: P52.1 P54.3 | length 500.9
  Bottom Layer w30: P52.1 4320,730 4455,595 P54.3
IN+_IOS: P22.1 P29.2 P32.2 R18.2 | length 708.5
  Bottom Layer w20: P22.1 4355,2870 R18.2 4425,2860 4455,2890 ; P29.2 4490,2780 4455,2815 4455,2890 ; P32.2 4485,3110 4455,3080 4455,2890
IN+_IOS_1: P23.3 P30.1 | length 484
  Bottom Layer w20: P30.1 5050,3110 P23.3
IN+_IOS_2: P27.3 P33.1 | length 663.7
  Bottom Layer w30: P33.1 4665,2650 4855,2460 P27.3
IN+_VOS: P13.2 P17.2 R4.2 R12.1 | length 2415.7
  Bottom Layer w30: R4.2@150,3105 140,3095 140,3087.43 130,3077.43 130,3045 ; P13.2 235,2600 150,2685 150,2686.22 130,2706.22 ; P17.2 140,3035 130,3045 ; R12.1@1070,2040 380,2040 130,2290 130,2706.22 ; 130,2706.22 130,3045
IN+_VOS_1: P8.3 P14.1 | length 980.7
  Bottom Layer w20: P14.1@474.4,3024.4 535,3085 995,3085 P8.3
IN+_VOS_2: P15.3 P18.1 | length 1012.4
  Bottom Layer w30: P18.1 570,2600 725,2445 1422.22,2445 P15.3
IN-_CMRR: P40.1 P56.1 R21.2 | length 829
  Bottom Layer w20: R21.2 165,726.72 176.72,715 P56.1@400,715 ; R21.2@170,840 135,875 135,1005 205,1075 P40.1
IN-_CMRR_1: P36.2 P41.2 | length 780.6
  Bottom Layer w20: P41.2 925,1075 P36.2
IN-_CMRR_2: P42.2 P57.2 | length 726.8
  Bottom Layer w20: P57.2 1055,830 P42.2
IN-_GBP_1: P46.1 P48.1 P48.2 R38.1 R38.2 | length 1009.2
  Bottom Layer w30: P48.1 P48.2 R38.2 ; R38.1 4875,1350 4945,1280 4945,1100 5030,1015 P46.1
IN-_GBP_2: P46.2 P54.1 P54.2 R39.1 R39.2 | length 814.7
  Bottom Layer w30: P54.2 P54.1 4572.5,795 R39.2 ; R39.1 4827.5,915 P46.2
IN-_IOS: P22.2 P29.1 P32.1 R14.2 | length 319.9
  Bottom Layer w30: P22.2 4360,3065 4360,3155 R14.2 4497.82,3160 4547.82,3210 P32.1
IN-_IOS_1: P23.2 P30.2 | length 484
  Bottom Layer w20: P30.2 5050,3210 P23.2
IN-_IOS_2: P27.2 P33.2 | length 663.7
  Bottom Layer w30: P33.2 4672.5,2872.5 4747.5,2872.5 4835,2785 4835,2655 4930,2560 P27.2
IN-_VOS: P13.1 P17.1 R3.2 | length 425.3
  Bottom Layer w30: R3.2 224.85,2935 P17.1 P13.1
IN-_VOS_1: P8.2 P14.2 pad.2@765,3017.5 pad.2@765,3152.5 R7.1 R7.2 | length 1127.6
  Top Layer w20: pad.2@765,3017.5 pad.2@765,3152.5
  Bottom Layer w20: P14.2 682.5,2935 R7.1
  Bottom Layer w30: R7.2 1385.32,3152.5 1417.82,3185 P8.2
IN-_VOS_2: P15.2 P18.2 | length 1006
  Bottom Layer w30: P18.2 570,2700 717.22,2552.78 P15.2
IOS_COMMON: P21.2 R17.2 R18.1 R20.1 | length 1353.1
  Bottom Layer w30: R17.2 4137.5,2962.5 4247.5,2962.5 P21.2 4250,2947.82 4275,2922.82 R18.1 4275,2455 4642.36,2087.64 R20.1
NetC7_1: C7.1 P19.1 R5.2 R12.2 U1.1 | length 2527.8
  Bottom Layer w20: R12.2 1277.5,1975 2655,1975 2741.58,2061.57 2741.58,2280 2741.58,2335 ; U1.1 2598.19,2715 2600,2713.19 2600,2666.72 2611.72,2655 2800,2655 2815,2640 2815,2605 R5.2 ; 2739.17,2335 2739.17,2514.17 C7.1 2790,2515 2820,2545 R5.2@2820,2595
NetC7_2: C7.2 C10.2 R6.2 U1.2 | length 512
  Bottom Layer w30: R6.2@2467.43,2677.57 2467.43,2747.43 2485,2765 U1.2 ; R6.2 2467.5,2617.5 2490,2595 C10.2 2555,2530 2575,2510 2640,2510 C7.2@2645,2515
NetC10_1: C10.1 R5.1 | length 90
  Bottom Layer w20: C10.1 R5.1
NetC15_1: C15.1 P31.1 R16.2 R20.2 U2.1 | length 2679.5
  Bottom Layer w30: R20.2 4933.51,2011.49 4965,1980 6350,1980 6468.43,2098.43 P31.1 6468.43,2496.57 C15.1@6420,2545 ; U2.1 6338.19,2726.18 6335,2722.99 6335,2565 6360,2540 6397.5,2540 C15.1 C15.1@6420,2545 ; R16.2 6585,2562.57 6567.43,2545 C15.1@6420,2545
NetC15_2: C15.2 C16.2 R19.2 U2.2 | length 345.9
  Bottom Layer w30: C15.2 C16.2 6262.5,2645 6262.5,2785 6271.32,2776.18 U2.2
NetC16_1: C16.1 R16.1 | length 94.8
  Bottom Layer w20: C16.1 6408.13,2645.63 R16.1
NetC25_1: C25.1 P44.1 R25.2 R27.2 U3.1 | length 3750
  Bottom Layer w30: R27.2 265,285 425,125 2595,125 2680,210 P44.1 2680,575 2570,685 R25.2 2393.19,841.81 2390,845 U3.1
NetC25_2: C25.2 R25.1 R26.2 U3.2 | length 327.9
  Bottom Layer w40: R25.1 2298.19,685 2267.5,715.69 R26.2 U3.2
NetC32_2: C32.2 P39.1 P39.2 R26.1 | length 312.4
  Bottom Layer w40: P39.1 P39.2 2031.7,921.7 2090.8,921.7 2117.5,895 R26.1 2131.25,893.75 2131.25,806.25 C32.2
NetC39_2: C39.2 P47.1 P47.2 P50.1 R28.1 | length 482.1
  Bottom Layer w20: P47.2 P47.1 C39.2 R28.1 5665,920 P50.1
NetP12_1: P12.1 P12.2 R6.1 | length 286.5
  Bottom Layer w20: P12.2 2305,2702.5 R6.1@2330,2677.5 ; R6.1@2330,2677.5 R6.1 2352.5,2655 R6.1@2330,2677.5
NetP21_1: P21.1 R14.1 R15.2 | length 225.4
  Bottom Layer w20: R15.2 P21.1 4250,3074.88 4275,3099.88 R14.1
NetP26_1: P26.1 P26.2 R19.1 | length 224.9
  Bottom Layer w20: P26.2 P26.1 6026.38,2726.72 6074.22,2726.72 R19.1@6122.5,2775
NetPW1_4: PW1.4 PW3.3 | length 316.9
  Bottom Layer w60: PW1.4 PW3.3
NetPW3_4: PW3.4 PW4.3 | length 316.9
  Bottom Layer w60: PW3.4 PW4.3
NULL: P1.1 PW1.2 PW2.2 PW3.2 PW4.2 PW5.2 PW6.2 | length 8009.4
  Bottom Layer w100: P1.1 635.59,5744.09 ; PW1.2 635.59,5744.09 ; 1875,5745 3042.05,5745 ; PW3.2 1997.5,5867.5 1874.09,5744.09 1830,5744.09 635.59,5744.09 ; PW4.2 3042.05,5745 ; PW2.2 4416.77,5745 ; PW6.2@5775,5903.23 5616.77,5745 ; PW5.2 6974.72,5854.72 6865,5745 5616.77,5745 ; 3042.05,5745 4371.77,5745 4416.77,5745 ; 4416.77,5745 5571.77,5745 5616.77,5745
OPA+: C4.2 C26.2 C30.2 C33.2 P3.2 P3.3 P7.3 P34.3 P37.1 P42.4 pad.2@1290,695 pad.2@1425,695 pad.2@1595,935 pad.2@1595,1070 R23.2 R33.1 R33.2 R36.1 R36.2 | length 2662.7
  Top Layer w20: pad.2@1290,695 pad.2@1425,695 ; pad.2@1595,932.5 pad.2@1595,1067.5
  Bottom Layer w40: P42.4 C33.2 1272.5,677.5 R36.1 ; R36.2 1595,865 R33.1 ; R33.2 1595,1382.5 C26.2 ; P34.3@1615,1676.34 C30.2 1620,1545 1625,1540 1625,1535 1642.5,1517.5 C26.2 ; P34.3 1617.75,1679.1 1729.1,1679.1 R23.2 ; P37.1 C26.2 ; P7.3 2601.58,4009.86 2641.72,4050 2861.57,4050 2885,4026.57 2885,3928.43 2908.43,3905 3090.25,3905 3113.68,3928.43 3113.68,3983.68 P3.2 ; P3.2@3112.11,3985 P3.3
OPA-: C3.2 C27.2 C31.2 C34.2 P5.2 P5.3 P7.1 P34.1 P36.4 P43.4 R2.1 R2.2 R22.2 | length 4645.2
  Bottom Layer w20: P36.4 C27.2@1275,1130 ; C31.2 1270,1775 C31.2@1277.5,1767.5 ; 1295,1780 1417.5,1780 1420,1777.5 P34.1 1420,1663.19 1345,1588.19 1345,1230 1285,1170 C27.2 1285,1082.5 1342.5,1025 1342.5,467.5 1400.5,409.5 1589.5,409.5 1636.72,456.72 1636.72,496.72 C34.2 1642.5,502.5 1732.5,502.5 P43.4
  Bottom Layer w40: P7.1 2799.21,3879.21 2799.21,3780.79 C3.2 ; P7.1@2800,3890 2845,3845 R2.1@4062.5,3845 ; R2.2 4485,3840 4545,3900 4545,4045 4595,4095 4940,4095 4975,4060 P5.2 P5.3
OUT_CMRR_1: P36.1 P38.1 pad.2@1295,1285 pad.2@1430,1285 R34.1 R34.2 | length 1061.8
  Top Layer w20: pad.2@1295,1285 pad.2@1430,1285
  Bottom Layer w20: R34.2 1490,1225 1490,1040 1515,1015 P38.1
  Bottom Layer w30: P36.1 1187.5,1422.5 1262.5,1422.5 1295,1390 R34.1
OUT_CMRR_2: P38.2 P42.1 R35.1 R35.2 | length 720.8
  Bottom Layer w20: P42.1 1180.23,805.23 1180.23,860.23 1215,895 R35.2 ; R35.1 1517.5,985 1790,985 1860,915 P38.2
OUT_IOS_1: P23.1 P25.1 pad.2@5247.5,3150 pad.2@5382.5,3150 R30.1 R30.2 | length 1177.5
  Top Layer w20: pad.2@5252.5,3150 pad.2@5387.5,3150
  Bottom Layer w20: R30.1 5402.5,3130 5402.5,3120.78 5405,3118.28 5405,2845 5437.5,2812.5 5907.01,2812.5 P25.1
  Bottom Layer w30: P23.1 5220,3240 5247.5,3212.5 R30.2
OUT_IOS_2: P25.2 P27.1 pad.2@5235,2720 pad.2@5370,2720 R31.1 R31.2 | length 895.8
  Top Layer w20: pad.2@5227.5,2720 pad.2@5362.5,2720
  Bottom Layer w20: R31.1 5432.5,2782.5 5727.5,2782.5 5795,2715 5909.51,2715 P25.2
  Bottom Layer w30: P27.1 5128.61,2668.61 5128.61,2702.43 5146.18,2720 R31.2
OUT_VOS_1: P8.1 P11.1 pad.2@1537.5,3235 pad.2@1672.5,3235 R8.1 R8.2 | length 1156.1
  Top Layer w20: pad.2@1537.5,3235 pad.2@1672.5,3235
  Bottom Layer w20: R8.2 1745,3162.5 1745,2865 1780,2830 2140,2830 P11.1
  Bottom Layer w30: P8.1 1475,3240 pad.2@1538.12,3240
OUT_VOS_2: P11.2 P15.1 pad.2@1557.5,2795 pad.2@1692.5,2795 R9.1 R9.2 | length 888.3
  Top Layer w30: pad.2@1557.5,2795 pad.2@1692.5,2795
  Bottom Layer w20: pad.2@1692.5,2790 1702.5,2800 2190,2800 P11.2
  Bottom Layer w30: P15.1 1430,2740 1485,2795 R9.1
PHASE: P1.3 PW1.1 PW2.1 PW3.1 PW4.1 PW5.1 PW6.1 | length 8240
  Bottom Layer w100: P1.3 1242.68,6055.91 ; PW1.1 1242.68,6055.91 ; PW3.1 2292.78,5922.22 2159.09,6055.91 ; PW4.1 3342.87,6055.91 ; PW2.1 4717.6,6055.91 ; PW6.1@6070.28,5903.23 5917.6,6055.91 ; PW5.1 7117.32,6055.91 5917.6,6055.91 ; 1242.68,6055.91 2159.09,6055.91 ; 2159.09,6055.91 3342.87,6055.91 ; 3342.87,6055.91 4717.6,6055.91 ; 4717.6,6055.91 5917.6,6055.91
pads on no net: C1.0 C2.0 C3.0 C4.0 C5.0 C6.0 C7.0 C8.0 C9.0 C10.0 C11.0 C12.0 C13.0 C14.0 C15.0 C16.0 C17.0 C18.0 C19.0 C20.0 C21.0 C22.0 C23.0 C24.0 C25.0 C26.0 C27.0 C28.0 C29.0 C30.0 C31.0 C32.0 C33.0 C34.0 C35.0 C36.0 C37.0 C38.0 C39.0 C40.0 C41.0 C42.0 C43.0 P1.2 P9.2 P9.3 P9.4 P15.5 P15.6 P15.7 P16.1 P16.2 P16.3 P16.5 P16.6 P16.7 P24.2 P24.3 P24.4 P27.5 P27.6 P27.7 P28.1 P28.2 P28.3 P28.5 P28.6 P28.7 P37.2 P37.3 P37.4 P42.5 P42.6 P42.7 P43.1 P43.2 P43.3 P43.5 P43.6 P43.7 P49.2 P49.3 P49.4 P54.5 P54.6 P54.7 P55.1 P55.2 P55.3 P55.5 P55.6 P55.7 R1.0 R2.0 R3.0 R4.0 R5.0 R6.0 R7.0 R8.0 R9.0 R10.0 R11.0 R12.0 R13.0 R14.0 R15.0 R16.0 R17.0 R18.0 R19.0 R20.0 R21.0 R22.0 R23.0 R24.0 R25.0 R26.0 R27.0 R28.0 R29.0 R30.0 R31.0 R32.0 R33.0 R34.0 R35.0 R36.0 R37.0 R38.0 R39.0 U1.4@2685,2738.82 U1.4@2685,2841.18 U1.5 U1.6 U1.7 U2.4@6465,2750 U2.4@6465,2852.36 U2.5 U2.6 U2.7 U3.4@2470,868.82 U3.4@2470,971.18 U3.5 U3.6 U3.7

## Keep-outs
Keep-Out Layer:
  lines w10: 5,1925 3010,1925 3995,1925 ; 5,3670 7755,3670 ; 3965,5 7755,5 7755,6150 5,6150 5,5 2075,5 3995,5 3995,1925 ; 3995,3670 3995,1925 ; 7755,1925 3995,1925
